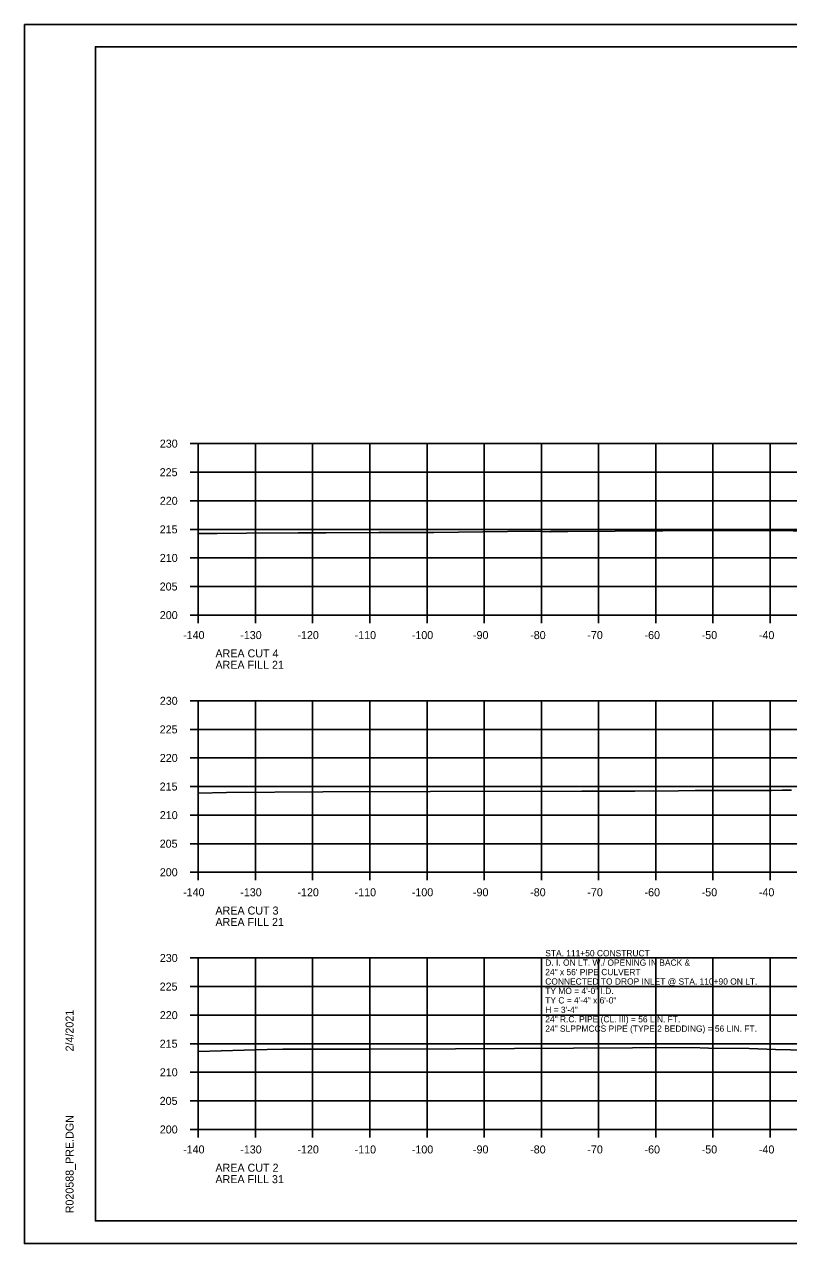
# Model space of a CAD drawing. Extents: x 1368968 to 1369915, y 377395 to 380381.
# Drawn here: x 1369581.4 to 1369715, y 377608 to 377821.4 of the extents above; entities that cross this region are included whole.
import ezdxf

# ---------------------------------------------------------------- set-up
doc = ezdxf.new("R2010")
doc.units = 0
for name, color, linetype in [('Default', 7, 'Continuous'), ('S_BREAKLINE_ANNOT', 7, 'Continuous'), ('S_BRIDGE', 7, 'Continuous'), ('S_BRIDGE_ANNOT', 7, 'Continuous'), ('S_CTL_TABLE', 7, 'Continuous'), ('S_DITCHLINE_ANNOT', 7, 'Continuous'), ('S_DROP_INLET', 7, 'Continuous')]:
    doc.layers.add(name, color=color, linetype=linetype)

msp = doc.modelspace()

# ---------------------------------------------------------------- linework, layer by layer
at = {"layer": 'S_BREAKLINE_ANNOT'}
for p, q in [((1369610.38, 377748.01), (1369611.78, 377748.01)), ((1369611.78, 377718.01), (1369611.78, 377748.01)), ((1369610.38, 377743.01), (1369611.78, 377743.01)), ((1369610.38, 377738.01), (1369611.78, 377738.01)), ((1369610.38, 377733.01), (1369611.78, 377733.01)), ((1369610.38, 377728.01), (1369611.78, 377728.01)), ((1369610.38, 377723.01), (1369611.78, 377723.01)), ((1369610.38, 377718.01), (1369611.78, 377718.01)), ((1369611.78, 377718.01), (1369891.78, 377718.01)), ((1369611.78, 377716.61), (1369611.78, 377718.01)), ((1369621.78, 377716.61), (1369621.78, 377718.01)), ((1369631.78, 377716.61), (1369631.78, 377718.01)), ((1369641.78, 377716.61), (1369641.78, 377718.01)), ((1369651.78, 377716.61), (1369651.78, 377718.01)), ((1369661.78, 377716.61), (1369661.78, 377718.01)), ((1369671.78, 377716.61), (1369671.78, 377718.01)), ((1369681.78, 377716.61), (1369681.78, 377718.01)), ((1369691.78, 377716.61), (1369691.78, 377718.01)), ((1369701.78, 377716.61), (1369701.78, 377718.01)), ((1369711.78, 377716.61), (1369711.78, 377718.01)), ((1369610.38, 377703.01), (1369611.78, 377703.01)), ((1369611.78, 377673.01), (1369611.78, 377703.01)), ((1369610.38, 377698.01), (1369611.78, 377698.01)), ((1369610.38, 377693.01), (1369611.78, 377693.01)), ((1369610.38, 377688.01), (1369611.78, 377688.01)), ((1369610.38, 377683.01), (1369611.78, 377683.01)), ((1369610.38, 377678.01), (1369611.78, 377678.01)), ((1369610.38, 377673.01), (1369611.78, 377673.01)), ((1369611.78, 377673.01), (1369891.78, 377673.01)), ((1369611.78, 377671.61), (1369611.78, 377673.01)), ((1369621.78, 377671.61), (1369621.78, 377673.01)), ((1369631.78, 377671.61), (1369631.78, 377673.01)), ((1369641.78, 377671.61), (1369641.78, 377673.01)), ((1369651.78, 377671.61), (1369651.78, 377673.01)), ((1369661.78, 377671.61), (1369661.78, 377673.01)), ((1369671.78, 377671.61), (1369671.78, 377673.01)), ((1369681.78, 377671.61), (1369681.78, 377673.01)), ((1369691.78, 377671.61), (1369691.78, 377673.01)), ((1369701.78, 377671.61), (1369701.78, 377673.01)), ((1369711.78, 377671.61), (1369711.78, 377673.01)), ((1369610.38, 377658.01), (1369611.78, 377658.01)), ((1369611.78, 377628.01), (1369611.78, 377658.01)), ((1369610.38, 377653.01), (1369611.78, 377653.01)), ((1369610.38, 377648.01), (1369611.78, 377648.01)), ((1369610.38, 377643.01), (1369611.78, 377643.01)), ((1369610.38, 377638.01), (1369611.78, 377638.01)), ((1369610.38, 377633.01), (1369611.78, 377633.01)), ((1369610.38, 377628.01), (1369611.78, 377628.01)), ((1369611.78, 377628.01), (1369891.78, 377628.01)), ((1369611.78, 377626.61), (1369611.78, 377628.01)), ((1369621.78, 377626.61), (1369621.78, 377628.01)), ((1369631.78, 377626.61), (1369631.78, 377628.01)), ((1369641.78, 377626.61), (1369641.78, 377628.01)), ((1369651.78, 377626.61), (1369651.78, 377628.01)), ((1369661.78, 377626.61), (1369661.78, 377628.01)), ((1369671.78, 377626.61), (1369671.78, 377628.01)), ((1369681.78, 377626.61), (1369681.78, 377628.01)), ((1369691.78, 377626.61), (1369691.78, 377628.01)), ((1369701.78, 377626.61), (1369701.78, 377628.01)), ((1369711.78, 377626.61), (1369711.78, 377628.01))]:
    msp.add_line(p, q, dxfattribs=at)
at = {"layer": 'S_BRIDGE_ANNOT'}
for p, q in [((1369593.78, 377817.47), (1369909.96, 377817.47)), ((1369593.78, 377612.01), (1369593.78, 377817.47)), ((1369593.78, 377612.01), (1369593.78, 377612.01)), ((1369909.96, 377612.01), (1369593.78, 377612.01))]:
    msp.add_line(p, q, dxfattribs=at)
at = {"layer": 'S_CTL_TABLE'}
for points in [[(1369611.78, 377732.29), (1369615.1, 377732.3), (1369620.23, 377732.32), (1369629.23, 377732.38), (1369634.12, 377732.4), (1369643.35, 377732.46), (1369647.66, 377732.45), (1369652.95, 377732.47), (1369665.86, 377732.66), (1369670.19, 377732.68), (1369673.34, 377732.6), (1369673.47, 377732.62), (1369676.43, 377732.64), (1369701.27, 377732.8), (1369702.06, 377732.8), (1369702.92, 377732.84), (1369710.83, 377732.81), (1369711.88, 377732.82), (1369719.72, 377732.7)], [(1369611.78, 377686.84), (1369616.71, 377686.99), (1369633.58, 377687.07), (1369652.37, 377687.16), (1369678.85, 377687.18), (1369688.1, 377687.22), (1369695.74, 377687.28), (1369698.66, 377687.31), (1369698.87, 377687.32), (1369702.73, 377687.31), (1369705.69, 377687.3), (1369708.93, 377687.33), (1369712, 377687.32), (1369713.95, 377687.36), (1369715.55, 377687.38)], [(1369611.78, 377641.64), (1369623.84, 377642.01), (1369626.54, 377642.03), (1369629.54, 377642.04), (1369641.88, 377642.05), (1369656.77, 377642.11), (1369698.05, 377642.34), (1369700.99, 377642.26), (1369708.12, 377642.15), (1369712.75, 377642.01), (1369720.68, 377641.83)]]:
    msp.add_lwpolyline(points, dxfattribs=at)
at = {"layer": 'S_DITCHLINE_ANNOT'}
for p, q in [((1369611.78, 377748.01), (1369891.78, 377748.01)), ((1369611.78, 377718.01), (1369611.78, 377748.01)), ((1369621.78, 377718.01), (1369621.78, 377748.01)), ((1369631.78, 377718.01), (1369631.78, 377748.01)), ((1369641.78, 377718.01), (1369641.78, 377748.01)), ((1369651.78, 377718.01), (1369651.78, 377748.01)), ((1369661.78, 377718.01), (1369661.78, 377748.01)), ((1369671.78, 377718.01), (1369671.78, 377748.01)), ((1369681.78, 377718.01), (1369681.78, 377748.01)), ((1369691.78, 377718.01), (1369691.78, 377748.01)), ((1369701.78, 377718.01), (1369701.78, 377748.01)), ((1369711.78, 377718.01), (1369711.78, 377748.01)), ((1369611.78, 377743.01), (1369891.78, 377743.01)), ((1369611.78, 377738.01), (1369891.78, 377738.01)), ((1369611.78, 377733.01), (1369891.78, 377733.01)), ((1369611.78, 377728.01), (1369891.78, 377728.01)), ((1369611.78, 377723.01), (1369891.78, 377723.01)), ((1369611.78, 377718.01), (1369891.78, 377718.01)), ((1369611.78, 377703.01), (1369891.78, 377703.01)), ((1369611.78, 377673.01), (1369611.78, 377703.01)), ((1369621.78, 377673.01), (1369621.78, 377703.01)), ((1369631.78, 377673.01), (1369631.78, 377703.01)), ((1369641.78, 377673.01), (1369641.78, 377703.01)), ((1369651.78, 377673.01), (1369651.78, 377703.01)), ((1369661.78, 377673.01), (1369661.78, 377703.01)), ((1369671.78, 377673.01), (1369671.78, 377703.01)), ((1369681.78, 377673.01), (1369681.78, 377703.01)), ((1369691.78, 377673.01), (1369691.78, 377703.01)), ((1369701.78, 377673.01), (1369701.78, 377703.01)), ((1369711.78, 377673.01), (1369711.78, 377703.01)), ((1369611.78, 377698.01), (1369891.78, 377698.01)), ((1369611.78, 377693.01), (1369891.78, 377693.01)), ((1369611.78, 377688.01), (1369891.78, 377688.01)), ((1369611.78, 377683.01), (1369891.78, 377683.01)), ((1369611.78, 377678.01), (1369891.78, 377678.01)), ((1369611.78, 377673.01), (1369891.78, 377673.01)), ((1369611.78, 377658.01), (1369891.78, 377658.01)), ((1369611.78, 377628.01), (1369611.78, 377658.01)), ((1369621.78, 377628.01), (1369621.78, 377658.01)), ((1369631.78, 377628.01), (1369631.78, 377658.01)), ((1369641.78, 377628.01), (1369641.78, 377658.01)), ((1369651.78, 377628.01), (1369651.78, 377658.01)), ((1369661.78, 377628.01), (1369661.78, 377658.01)), ((1369671.78, 377628.01), (1369671.78, 377658.01)), ((1369681.78, 377628.01), (1369681.78, 377658.01)), ((1369691.78, 377628.01), (1369691.78, 377658.01)), ((1369701.78, 377628.01), (1369701.78, 377658.01)), ((1369711.78, 377628.01), (1369711.78, 377658.01)), ((1369611.78, 377653.01), (1369891.78, 377653.01)), ((1369611.78, 377648.01), (1369891.78, 377648.01)), ((1369611.78, 377643.01), (1369891.78, 377643.01)), ((1369611.78, 377638.01), (1369891.78, 377638.01)), ((1369611.78, 377633.01), (1369891.78, 377633.01)), ((1369611.78, 377628.01), (1369891.78, 377628.01))]:
    msp.add_line(p, q, dxfattribs=at)
at = {"layer": 'S_DROP_INLET'}
for p, q in [((1369581.38, 377821.37), (1369914.71, 377821.37)), ((1369581.38, 377608.04), (1369914.71, 377608.04))]:
    msp.add_line(p, q, dxfattribs=at)
for points in [[(1369581.37, 377821.37), (1369914.71, 377821.37), (1369914.71, 377608.03), (1369581.37, 377608.03)], [(1369827.7, 377817.47), (1369827.7, 377807.59), (1369863.43, 377807.59), (1369863.43, 377804.67), (1369886.63, 377804.67), (1369886.63, 377780.34), (1369909.96, 377780.34), (1369909.96, 377612.01), (1369593.78, 377612.01), (1369593.78, 377817.47)]]:
    msp.add_lwpolyline(points, close=True, dxfattribs=at)

# ---------------------------------------------------------------- texts
at = {"layer": 'Default'}
for s, p in [('STA. 111+50 CONSTRUCT', (1369672.46, 377658.3)), ('D. I. ON LT. W./ OPENING IN BACK &', (1369672.46, 377656.65)), ('24" x 56\' PIPE CULVERT', (1369672.46, 377655)), ('CONNECTED TO DROP INLET @ STA. 110+90 ON LT.', (1369672.46, 377653.35)), ('TY MO = 4\'-0" I.D.', (1369672.46, 377651.7)), ('TY C = 4\'-4" x 6\'-0"', (1369672.46, 377650.05)), ('H = 3\'-4"', (1369672.46, 377648.4)), ('24" R.C. PIPE (CL. III) = 56 LIN. FT.', (1369672.46, 377646.75)), ('24" SLPPMCCS PIPE (TYPE 2 BEDDING) = 56 LIN. FT.', (1369672.46, 377645.1))]:
    msp.add_text(s, height=1.1, dxfattribs=at).set_placement(p)
at = {"layer": 'S_BRIDGE'}
for s, p in [('230', (1369605.05, 377747.31)), ('225', (1369605.03, 377742.31)), ('220', (1369605.05, 377737.31)), ('215', (1369605.03, 377732.31)), ('210', (1369605.05, 377727.31)), ('205', (1369605.03, 377722.31)), ('200', (1369605.05, 377717.31)), ('-140', (1369609.12, 377713.81)), ('-130', (1369619.12, 377713.81)), ('-120', (1369629.12, 377713.81)), ('-110', (1369639.12, 377713.81)), ('-100', (1369649.12, 377713.81)), ('-90', (1369659.82, 377713.81)), ('-80', (1369669.82, 377713.81)), ('-70', (1369679.82, 377713.81)), ('-60', (1369689.82, 377713.81)), ('-50', (1369699.82, 377713.81)), ('-40', (1369709.82, 377713.81)), ('AREA CUT 4', (1369614.78, 377710.61)), ('AREA FILL 21', (1369614.78, 377708.61)), ('230', (1369605.05, 377702.31)), ('225', (1369605.03, 377697.31)), ('220', (1369605.05, 377692.31)), ('215', (1369605.03, 377687.31)), ('210', (1369605.05, 377682.31)), ('205', (1369605.03, 377677.31)), ('200', (1369605.05, 377672.31)), ('-140', (1369609.12, 377668.81)), ('-130', (1369619.12, 377668.81)), ('-120', (1369629.12, 377668.81)), ('-110', (1369639.12, 377668.81)), ('-100', (1369649.12, 377668.81)), ('-90', (1369659.82, 377668.81)), ('-80', (1369669.82, 377668.81)), ('-70', (1369679.82, 377668.81)), ('-60', (1369689.82, 377668.81)), ('-50', (1369699.82, 377668.81)), ('-40', (1369709.82, 377668.81)), ('AREA CUT 3', (1369614.78, 377665.61)), ('AREA FILL 21', (1369614.78, 377663.61)), ('230', (1369605.05, 377657.31)), ('225', (1369605.03, 377652.31)), ('220', (1369605.05, 377647.31)), ('215', (1369605.03, 377642.31)), ('210', (1369605.05, 377637.31)), ('205', (1369605.03, 377632.31)), ('200', (1369605.05, 377627.31)), ('-140', (1369609.12, 377623.81)), ('-130', (1369619.12, 377623.81)), ('-120', (1369629.12, 377623.81)), ('-110', (1369639.12, 377623.81)), ('-100', (1369649.12, 377623.81)), ('-90', (1369659.82, 377623.81)), ('-80', (1369669.82, 377623.81)), ('-70', (1369679.82, 377623.81)), ('-60', (1369689.82, 377623.81)), ('-50', (1369699.82, 377623.81)), ('-40', (1369709.82, 377623.81)), ('AREA CUT 2', (1369614.78, 377620.61)), ('AREA FILL 31', (1369614.78, 377618.61))]:
    msp.add_text(s, height=1.4, dxfattribs=at).set_placement(p)
at = {"layer": 'S_BRIDGE_ANNOT'}
for s, p in [('2/4/2021', (1369589.97, 377641.66)), ('R020588_PRE.DGN', (1369589.97, 377613.34))]:
    msp.add_text(s, height=1.4, rotation=90, dxfattribs=at).set_placement(p)

doc.saveas('drawing.dxf')
